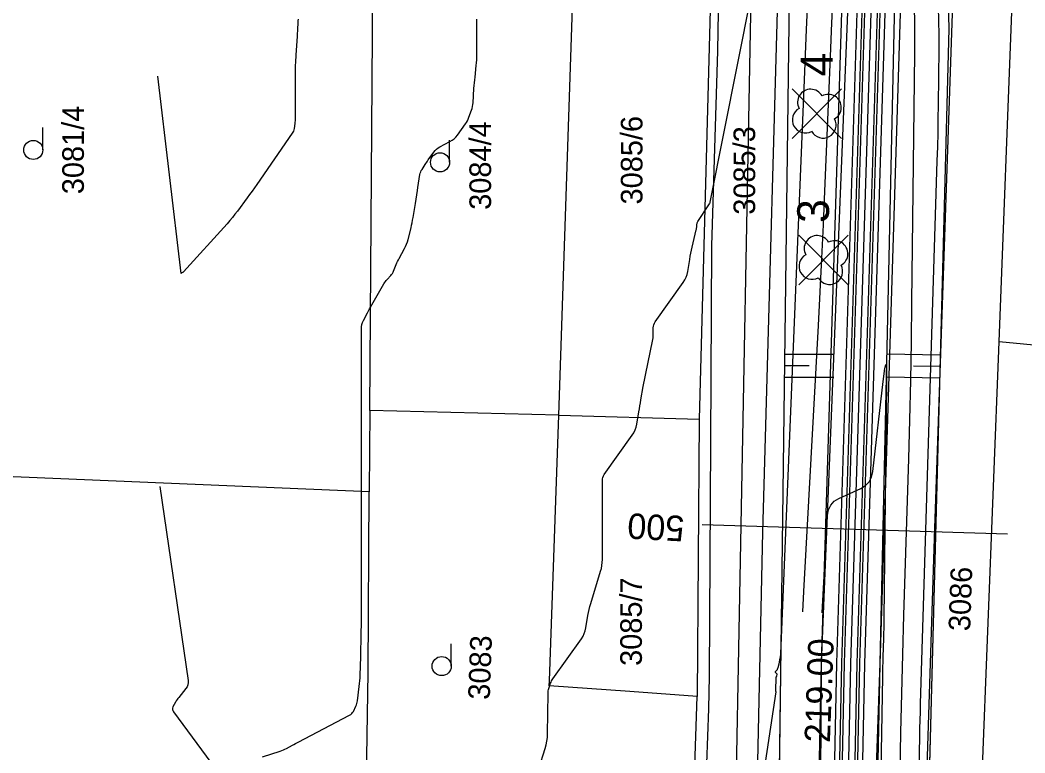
# Model space of a CAD drawing. Extents: x -534410 to -534262, y -1190162 to -1189584.
# Drawn here: x -534356.09 to -534316.62, y -1190081.68 to -1190052.88 of the extents above; entities that cross this region are included whole.
import ezdxf

# ---------------------------------------------------------------- set-up
doc = ezdxf.new("R2010")
doc.units = 0
for name, color, linetype in [('07_ELEKTRO', 7, 'Continuous'), ('30', 7, 'Continuous'), ('31', 7, 'Continuous'), ('40', 7, 'Continuous'), ('_linie', 7, 'Continuous'), ('_N_osa', 7, 'Continuous'), ('_N_tenká', 7, 'Continuous'), ('_N_tenká_velmi', 7, 'Continuous'), ('_N_text', 7, 'Continuous'), ('_přístup', 7, 'Continuous'), ('_tenka', 7, 'Continuous'), ('_velmi_tenka', 7, 'Continuous'), ('Default', 7, 'Continuous'), ('Hranice parcel', 7, 'Continuous'), ('Parcelní čísla', 7, 'Continuous'), ('Značky kultur', 7, 'Continuous')]:
    doc.layers.add(name, color=color, linetype=linetype)

msp = doc.modelspace()

# ---------------------------------------------------------------- linework, layer by layer
at = {"layer": '07_ELEKTRO'}
msp.add_lwpolyline([(-534329.31, -1190087.46), (-534329.03, -1190079.95), (-534329.01, -1190078.66), (-534328.95, -1190069.47), (-534328.91, -1190061.75), (-534328.68, -1190054.09), (-534328.55, -1190046.44), (-534328.261, -1190025.497), (-534332.174, -1190007.081), (-534334.321, -1190004.167), (-534336.852, -1190002.737), (-534339.713, -1190001.803)], dxfattribs=at)
at = {"layer": '30'}
for points in [[(-534321.439, -1190024.07), (-534321.403, -1190024.729), (-534321.16, -1190031.821), (-534321.095, -1190033.569), (-534321.018, -1190035.317), (-534320.93, -1190037.065), (-534320.831, -1190038.812), (-534320.052, -1190051.814), (-534320.024, -1190052.363), (-534320.005, -1190052.912), (-534319.997, -1190053.461), (-534319.998, -1190054.011), (-534320.024, -1190056.21), (-534320.031, -1190056.76), (-534320.042, -1190057.31), (-534320.054, -1190057.86), (-534320.07, -1190058.409), (-534320.726, -1190079.747), (-534320.736, -1190080.069), (-534320.744, -1190080.391), (-534320.751, -1190080.713), (-534320.757, -1190081.035), (-534320.78, -1190082.323)], [(-534328.187, -1190091.169), (-534326.393, -1190079.271), (-534326.393, -1190079.267), (-534326.393, -1190079.263), (-534326.394, -1190079.26), (-534326.395, -1190079.256), (-534326.4, -1190079.241), (-534326.401, -1190079.237), (-534326.402, -1190079.234), (-534326.402, -1190079.23), (-534326.403, -1190079.226), (-534326.385, -1190078.709), (-534326.384, -1190078.703), (-534326.383, -1190078.696), (-534326.381, -1190078.69), (-534326.378, -1190078.684), (-534326.357, -1190078.649), (-534326.355, -1190078.646), (-534326.343, -1190078.602), (-534326.342, -1190078.595), (-534326.343, -1190078.588), (-534326.346, -1190078.582), (-534326.35, -1190078.577), (-534326.405, -1190078.527), (-534326.413, -1190078.517), (-534326.416, -1190078.506), (-534326.414, -1190078.495), (-534326.407, -1190078.484), (-534326.342, -1190078.407), (-534326.34, -1190078.403), (-534326.338, -1190078.4), (-534326.336, -1190078.396), (-534326.335, -1190078.392), (-534326.33, -1190078.372), (-534326.327, -1190078.361), (-534326.321, -1190078.34), (-534326.318, -1190078.33), (-534326.314, -1190078.321), (-534326.301, -1190078.29), (-534326.298, -1190078.283), (-534326.296, -1190078.275), (-534326.291, -1190078.255), (-534326.288, -1190078.243), (-534326.278, -1190078.211), (-534326.276, -1190078.204), (-534326.274, -1190078.197), (-534326.273, -1190078.19), (-534326.271, -1190078.183), (-534326.227, -1190077.952), (-534326.22, -1190077.911), (-534326.214, -1190077.87), (-534326.21, -1190077.829), (-534326.208, -1190077.787), (-534325.27, -1190055.236), (-534325.189, -1190053.257), (-534325.109, -1190051.279)], [(-534346.562, -1190081.825), (-534345.87, -1190081.605), (-534345.807, -1190081.583), (-534345.746, -1190081.559), (-534345.685, -1190081.531), (-534345.626, -1190081.501), (-534345.393, -1190081.375), (-534345.335, -1190081.343), (-534345.276, -1190081.312), (-534345.217, -1190081.281), (-534345.159, -1190081.25), (-534343.147, -1190080.2), (-534343.099, -1190080.171), (-534343.059, -1190080.135), (-534343.024, -1190080.093), (-534342.997, -1190080.045), (-534342.898, -1190079.841), (-534342.875, -1190079.79), (-534342.857, -1190079.737), (-534342.843, -1190079.682), (-534342.834, -1190079.627), (-534342.762, -1190079.068), (-534342.749, -1190078.956), (-534342.739, -1190078.844), (-534342.732, -1190078.732), (-534342.727, -1190078.619), (-534342.708, -1190077.898), (-534342.708, -1190077.88), (-534342.708, -1190077.862), (-534342.708, -1190077.827), (-534342.707, -1190077.809), (-534342.707, -1190077.791), (-534342.689, -1190077.086), (-534342.687, -1190076.965), (-534342.685, -1190076.844), (-534342.683, -1190076.724), (-534342.683, -1190076.603), (-534342.683, -1190065.019), (-534342.678, -1190064.933), (-534342.663, -1190064.849), (-534342.638, -1190064.769), (-534342.602, -1190064.69), (-534342.44, -1190064.382), (-534342.4, -1190064.305), (-534342.358, -1190064.229), (-534342.316, -1190064.153), (-534342.273, -1190064.077), (-534341.796, -1190063.249), (-534341.768, -1190063.204), (-534341.738, -1190063.161), (-534341.706, -1190063.119), (-534341.671, -1190063.079), (-534341.528, -1190062.923), (-534341.494, -1190062.882), (-534341.464, -1190062.839), (-534341.439, -1190062.794), (-534341.417, -1190062.746), (-534341.309, -1190062.482), (-534341.284, -1190062.423), (-534341.257, -1190062.363), (-534341.228, -1190062.305), (-534341.198, -1190062.248), (-534340.985, -1190061.861), (-534340.942, -1190061.777), (-534340.904, -1190061.69), (-534340.873, -1190061.601), (-534340.847, -1190061.51), (-534340.732, -1190061.043), (-534340.709, -1190060.944), (-534340.687, -1190060.844), (-534340.668, -1190060.743), (-534340.65, -1190060.642), (-534340.562, -1190060.092), (-534340.534, -1190059.922), (-534340.479, -1190059.581), (-534340.461, -1190059.467), (-534340.379, -1190058.955), (-534340.367, -1190058.901), (-534340.35, -1190058.849), (-534340.328, -1190058.799), (-534340.3, -1190058.751), (-534340.178, -1190058.564), (-534340.147, -1190058.518), (-534340.116, -1190058.471), (-534340.084, -1190058.425), (-534340.052, -1190058.38), (-534339.837, -1190058.075), (-534339.787, -1190058.012), (-534339.731, -1190057.957), (-534339.668, -1190057.908), (-534339.6, -1190057.867), (-534339.204, -1190057.658), (-534339.118, -1190057.606), (-534339.039, -1190057.546), (-534338.969, -1190057.477), (-534338.905, -1190057.399), (-534338.593, -1190056.966), (-534338.551, -1190056.904), (-534338.515, -1190056.84), (-534338.483, -1190056.773), (-534338.456, -1190056.704), (-534338.356, -1190056.422), (-534338.334, -1190056.351), (-534338.316, -1190056.279), (-534338.304, -1190056.206), (-534338.296, -1190056.133), (-534338.259, -1190055.571), (-534338.251, -1190055.459), (-534338.241, -1190055.346), (-534338.231, -1190055.234), (-534338.218, -1190055.121), (-534338.166, -1190054.672), (-534338.154, -1190054.56), (-534338.146, -1190054.447), (-534338.141, -1190054.335), (-534338.14, -1190054.222), (-534338.14, -1190053.34), (-534338.14, -1190053.291), (-534338.141, -1190053.241), (-534338.141, -1190053.192), (-534338.143, -1190053.142), (-534338.148, -1190052.943), (-534338.149, -1190052.894), (-534338.15, -1190052.845)], [(-534324.582, -1190076.169), (-534324.371, -1190072.338), (-534324.333, -1190072.121), (-534324.245, -1190071.938), (-534324.108, -1190071.789), (-534323.919, -1190071.675), (-534323.067, -1190071.284), (-534322.878, -1190071.169), (-534322.734, -1190071.02), (-534322.638, -1190070.838), (-534322.588, -1190070.622), (-534322.186, -1190067.078), (-534322.121, -1190066.577), (-534322.076, -1190066.412), (-534322.053, -1190066.582), (-534322.05, -1190067.087), (-534322.157, -1190076.409), (-534322.16, -1190076.598), (-534322.163, -1190076.787), (-534322.168, -1190076.975), (-534322.173, -1190077.164), (-534322.196, -1190077.919), (-534322.202, -1190078.108), (-534322.206, -1190078.297), (-534322.211, -1190078.485), (-534322.214, -1190078.674), (-534322.64, -1190103.1)], [(-534350.597, -1190071.215), (-534349.487, -1190078.826), (-534349.483, -1190078.915), (-534349.496, -1190078.999), (-534349.528, -1190079.078), (-534349.577, -1190079.152), (-534349.858, -1190079.496), (-534349.892, -1190079.539), (-534349.923, -1190079.584), (-534349.952, -1190079.631), (-534349.979, -1190079.679), (-534350.082, -1190079.873), (-534350.1, -1190079.921), (-534350.104, -1190079.968), (-534350.093, -1190080.014), (-534350.068, -1190080.059), (-534348.04, -1190082.803)]]:
    msp.add_lwpolyline(points, dxfattribs=at)
at = {"layer": '31'}
for points in [[(-534335.714, -1190082.285), (-534335.462, -1190081.509), (-534335.421, -1190081.363), (-534335.391, -1190081.216), (-534335.372, -1190081.066), (-534335.365, -1190080.915), (-534335.35, -1190079.342), (-534335.348, -1190079.29), (-534335.341, -1190079.24), (-534335.331, -1190079.189), (-534335.316, -1190079.14), (-534335.25, -1190078.943), (-534335.231, -1190078.895), (-534335.21, -1190078.848), (-534335.184, -1190078.803), (-534335.156, -1190078.76), (-534334.039, -1190077.197), (-534333.975, -1190077.095), (-534333.923, -1190076.988), (-534333.885, -1190076.877), (-534333.859, -1190076.759), (-534333.782, -1190076.28), (-534333.76, -1190076.161), (-534333.735, -1190076.042), (-534333.705, -1190075.925), (-534333.672, -1190075.808), (-534333.283, -1190074.54), (-534333.253, -1190074.427), (-534333.231, -1190074.313), (-534333.218, -1190074.197), (-534333.214, -1190074.08), (-534333.214, -1190073.506), (-534333.214, -1190073.374), (-534333.214, -1190073.241), (-534333.214, -1190072.977), (-534333.214, -1190072.911), (-534333.214, -1190072.845), (-534333.214, -1190072.778), (-534333.214, -1190072.712), (-534333.214, -1190072.448), (-534333.214, -1190072.315), (-534333.214, -1190072.183), (-534333.214, -1190071.506), (-534333.214, -1190071.374), (-534333.214, -1190071.241), (-534333.214, -1190070.977), (-534333.21, -1190070.912), (-534333.195, -1190070.851), (-534333.171, -1190070.792), (-534333.138, -1190070.737), (-534332.038, -1190069.196), (-534331.974, -1190069.095), (-534331.923, -1190068.989), (-534331.885, -1190068.877), (-534331.859, -1190068.76), (-534331.782, -1190068.282), (-534331.762, -1190068.162), (-534331.742, -1190068.043), (-534331.721, -1190067.924), (-534331.7, -1190067.804), (-534331.607, -1190067.281), (-534331.583, -1190067.154), (-534331.559, -1190067.027), (-534331.534, -1190066.9), (-534331.508, -1190066.774), (-534331.24, -1190065.505), (-534331.228, -1190065.439), (-534331.22, -1190065.374), (-534331.214, -1190065.308), (-534331.213, -1190065.242), (-534331.213, -1190064.977), (-534331.208, -1190064.912), (-534331.193, -1190064.851), (-534331.169, -1190064.792), (-534331.135, -1190064.737), (-534330.037, -1190063.195), (-534329.974, -1190063.094), (-534329.923, -1190062.988), (-534329.884, -1190062.877), (-534329.859, -1190062.76), (-534329.782, -1190062.284), (-534329.761, -1190062.165), (-534329.739, -1190062.047), (-534329.715, -1190061.928), (-534329.688, -1190061.811), (-534329.528, -1190061.128), (-534329.522, -1190061.1), (-534329.517, -1190061.072), (-534329.512, -1190061.044), (-534329.509, -1190061.016), (-534329.497, -1190060.902), (-534329.493, -1190060.874), (-534329.485, -1190060.847), (-534329.474, -1190060.821), (-534329.46, -1190060.796), (-534329.033, -1190060.14), (-534329.011, -1190060.107), (-534328.99, -1190060.074), (-534328.985, -1190060.065), (-534328.981, -1190060.057), (-534328.977, -1190060.047), (-534328.975, -1190060.038), (-534327.353, -1190051.869)], [(-534325.339, -1190076.14), (-534325.297, -1190075.335), (-534324.723, -1190064.883), (-534324.653, -1190063.563), (-534324.587, -1190062.243), (-534324.526, -1190060.922), (-534324.469, -1190059.601), (-534324.249, -1190054.317), (-534324.195, -1190052.996), (-534324.141, -1190051.675)], [(-534320.964, -1190052.178), (-534320.949, -1190053.183), (-534320.951, -1190054.188), (-534321.064, -1190063.973), (-534321.085, -1190065.511), (-534321.114, -1190067.048), (-534321.15, -1190068.585), (-534321.193, -1190070.122), (-534321.382, -1190076.27), (-534321.427, -1190077.807), (-534321.467, -1190079.344), (-534321.501, -1190080.881), (-534321.531, -1190082.418)], [(-534345.17, -1190052.846), (-534345.178, -1190052.913), (-534345.183, -1190052.981), (-534345.192, -1190053.254), (-534345.195, -1190053.323), (-534345.198, -1190053.391), (-534345.202, -1190053.459), (-534345.206, -1190053.527), (-534345.256, -1190054.246), (-534345.26, -1190054.306), (-534345.263, -1190054.366), (-534345.266, -1190054.426), (-534345.269, -1190054.485), (-534345.277, -1190054.725), (-534345.279, -1190054.785), (-534345.281, -1190054.845), (-534345.281, -1190054.904), (-534345.282, -1190054.964), (-534345.282, -1190056.743), (-534345.283, -1190056.794), (-534345.285, -1190056.844), (-534345.29, -1190056.895), (-534345.296, -1190056.945), (-534345.325, -1190057.147), (-534345.335, -1190057.196), (-534345.351, -1190057.243), (-534345.372, -1190057.288), (-534345.398, -1190057.331), (-534346.793, -1190059.347), (-534346.885, -1190059.479), (-534346.978, -1190059.61), (-534347.072, -1190059.741), (-534347.168, -1190059.87), (-534347.551, -1190060.387), (-534347.649, -1190060.515), (-534347.749, -1190060.64), (-534347.853, -1190060.763), (-534347.959, -1190060.883), (-534349.675, -1190062.776), (-534349.681, -1190062.782), (-534349.687, -1190062.787), (-534349.694, -1190062.792), (-534349.701, -1190062.796), (-534349.74, -1190062.82), (-534349.746, -1190062.824), (-534349.754, -1190062.831), (-534349.757, -1190062.835), (-534349.761, -1190062.843), (-534349.762, -1190062.842), (-534349.762, -1190062.841), (-534350.673, -1190055.087)]]:
    msp.add_lwpolyline(points, dxfattribs=at)
at = {"layer": '_linie'}
for points in [[(-534351.8, -1189951.99), (-534346.88, -1189964.25), (-534328.11, -1190005.55), (-534325.796, -1190021.686), (-534325.86, -1190050.97), (-534326.22, -1190078.56), (-534326.79, -1190120.4), (-534329.12, -1190134.93), (-534323.49, -1190133.89), (-534321.38, -1190121.46), (-534319.59, -1190053.22), (-534320.45, -1190021.195), (-534322.75, -1190003.33), (-534340.65, -1189960.04), (-534344.52, -1189948.89)], [(-534347.45, -1189950.137), (-534345.54, -1189954.54), (-534325.02, -1190005.35), (-534322.054, -1190021.393), (-534321.72, -1190051.56), (-534322.31, -1190078.15), (-534323.81, -1190120.37), (-534326.521, -1190134.45)], [(-534328.194, -1190134.759), (-534324.85, -1190120.45), (-534324.6, -1190078.17), (-534323.54, -1190051.92), (-534323.273, -1190021.516), (-534325.81, -1190005.43), (-534346.66, -1189954.59), (-534348.342, -1189950.518)]]:
    msp.add_lwpolyline(points, dxfattribs=at)
at = {"layer": '_N_osa'}
msp.add_lwpolyline([(-534327.357, -1190134.604), (-534324.33, -1190120.41), (-534323.455, -1190078.16), (-534322.63, -1190051.74), (-534322.663, -1190021.455), (-534325.415, -1190005.39), (-534346.1, -1189954.565), (-534347.892, -1189950.326)], dxfattribs=at)
at = {"layer": '_N_tenká'}
for points in [[(-534326.133, -1190134.378), (-534323.183, -1190120.543), (-534322.305, -1190078.19), (-534321.48, -1190051.757), (-534321.513, -1190021.356), (-534324.303, -1190005.072), (-534345.038, -1189954.124), (-534346.832, -1189949.878)], [(-534328.581, -1190134.83), (-534325.477, -1190120.277), (-534324.605, -1190078.13), (-534323.78, -1190051.723), (-534323.813, -1190021.553), (-534326.527, -1190005.708), (-534347.162, -1189955.006), (-534348.951, -1189950.773)]]:
    msp.add_lwpolyline(points, dxfattribs=at)
at = {"layer": '_N_tenká_velmi'}
for points in [[(-534326.985, -1190134.536), (-534323.981, -1190120.45), (-534323.105, -1190078.169), (-534322.28, -1190051.745), (-534322.313, -1190021.425), (-534325.076, -1190005.293), (-534345.777, -1189954.431), (-534347.569, -1189950.189)], [(-534326.772, -1190134.496), (-534323.781, -1190120.474), (-534322.905, -1190078.174), (-534322.08, -1190051.748), (-534322.113, -1190021.407), (-534324.883, -1190005.238), (-534345.592, -1189954.354), (-534347.385, -1189950.112)], [(-534327.943, -1190134.713), (-534324.879, -1190120.346), (-534324.005, -1190078.146), (-534323.18, -1190051.732), (-534323.213, -1190021.502), (-534325.947, -1190005.542), (-534346.608, -1189954.776), (-534348.398, -1189950.54)], [(-534327.73, -1190134.673), (-534324.679, -1190120.37), (-534323.805, -1190078.151), (-534322.98, -1190051.735), (-534323.013, -1190021.485), (-534325.754, -1190005.487), (-534346.423, -1189954.699), (-534348.214, -1189950.462)], [(-534327.623, -1190134.654), (-534324.579, -1190120.381), (-534323.705, -1190078.154), (-534322.88, -1190051.736), (-534322.913, -1190021.476), (-534325.657, -1190005.459), (-534346.331, -1189954.661), (-534348.122, -1189950.423)], [(-534327.091, -1190134.555), (-534324.081, -1190120.439), (-534323.205, -1190078.166), (-534322.38, -1190051.744), (-534322.413, -1190021.433), (-534325.173, -1190005.321), (-534345.869, -1189954.469), (-534347.661, -1189950.228)]]:
    msp.add_lwpolyline(points, dxfattribs=at)
at = {"layer": '_N_text'}
msp.add_lwpolyline([(-534317.294, -1190073.085), (-534329.288, -1190072.711)], dxfattribs=at)
at = {"layer": '_přístup'}
for p, q in [((-534323.817, -1190057.533), (-534325.763, -1190055.587)), ((-534325.763, -1190057.533), (-534323.817, -1190055.587)), ((-534325.503, -1190063.283), (-534323.557, -1190061.337)), ((-534323.557, -1190063.283), (-534325.503, -1190061.337))]:
    msp.add_line(p, q, dxfattribs=at)
msp.add_lwpolyline([(-534330.552, -1190135.191), (-534328.648, -1190119.819), (-534326.845, -1190024.247), (-534332.805, -1189999.297), (-534354.454, -1189948.317)], dxfattribs=at)
for centre in [(-534324.79, -1190056.56), (-534324.53, -1190062.31)]:
    msp.add_circle(centre, 0.000512, dxfattribs=at)
for centre, start, end in [((-534325.035, -1190056.111), 28.6209, 208.6209), ((-534324.341, -1190056.315), 298.6209, 118.6209), ((-534325.239, -1190056.805), 118.6209, 298.6209), ((-534324.545, -1190057.009), 208.6209, 28.6209), ((-534324.775, -1190061.861), 28.6209, 208.6209), ((-534324.081, -1190062.065), 298.6209, 118.6209), ((-534324.979, -1190062.555), 118.6209, 298.6209), ((-534324.285, -1190062.759), 208.6209, 28.6209)]:
    msp.add_arc(centre, 0.512, start, end, dxfattribs=at)
at = {"layer": '_tenka'}
for points in [[(-534351.8, -1189951.99), (-534346.88, -1189964.25), (-534328.11, -1190005.55), (-534325.796, -1190021.686), (-534325.86, -1190050.97), (-534326.22, -1190078.56), (-534326.79, -1190120.4), (-534329.12, -1190134.93), (-534323.49, -1190133.89), (-534321.38, -1190121.46), (-534319.59, -1190053.22), (-534320.45, -1190021.195), (-534322.75, -1190003.33), (-534340.65, -1189960.04), (-534344.52, -1189948.89)], [(-534327.55, -1190134.64), (-534323.49, -1190133.89), (-534321.38, -1190121.46), (-534319.59, -1190053.22), (-534320.45, -1190021.195), (-534322.75, -1190003.33), (-534340.65, -1189960.04), (-534344.52, -1189948.89)], [(-534347.45, -1189950.137), (-534345.54, -1189954.54), (-534325.02, -1190005.35), (-534322.054, -1190021.393), (-534321.72, -1190051.56), (-534322.31, -1190078.15), (-534323.81, -1190120.37), (-534326.521, -1190134.45)], [(-534347.45, -1189950.137), (-534345.54, -1189954.54), (-534325.02, -1190005.35), (-534322.054, -1190021.393), (-534321.72, -1190051.56), (-534322.31, -1190078.15), (-534323.81, -1190120.37), (-534326.521, -1190134.45)], [(-534328.194, -1190134.759), (-534324.85, -1190120.45), (-534324.6, -1190078.17), (-534323.54, -1190051.92), (-534323.273, -1190021.516), (-534325.81, -1190005.43), (-534346.66, -1189954.59), (-534348.342, -1189950.518)], [(-534328.194, -1190134.759), (-534324.85, -1190120.45), (-534324.6, -1190078.17), (-534323.54, -1190051.92), (-534323.273, -1190021.516), (-534325.81, -1190005.43), (-534346.66, -1189954.59), (-534348.342, -1189950.518)], [(-534351.8, -1189951.99), (-534346.88, -1189964.25), (-534328.11, -1190005.55), (-534325.796, -1190021.686), (-534325.86, -1190050.97), (-534326.22, -1190078.56), (-534326.79, -1190120.4), (-534329.12, -1190134.93), (-534327.55, -1190134.64)]]:
    msp.add_lwpolyline(points, dxfattribs=at)
at = {"layer": '_velmi_tenka'}
for p, q in [((-534326.063, -1190066.011), (-534324.128, -1190066.008)), ((-534319.931, -1190066.048), (-534322.043, -1190066.012)), ((-534326.062, -1190066.461), (-534325.095, -1190066.459)), ((-534319.938, -1190066.498), (-534320.994, -1190066.48)), ((-534326.061, -1190066.911), (-534324.126, -1190066.908)), ((-534319.946, -1190066.948), (-534322.058, -1190066.912))]:
    msp.add_line(p, q, dxfattribs=at)
at = {"layer": 'Default'}
for p, q in [((-534325.86, -1190050.97), (-534326.22, -1190078.56)), ((-534321.38, -1190121.46), (-534319.59, -1190053.22)), ((-534326.22, -1190078.56), (-534326.79, -1190120.4))]:
    msp.add_line(p, q, dxfattribs=at)
msp.add_lwpolyline([(-534319.59, -1190053.22), (-534320.45, -1190021.195), (-534322.75, -1190003.33)], dxfattribs=at)
at = {"layer": 'Hranice parcel'}
for p, q in [((-534334.93, -1190068.41), (-534334.16, -1190045.57)), ((-534328.79, -1190045.66), (-534329.41, -1190068.56)), ((-534318.39, -1190085.1), (-534317.63, -1190065.52)), ((-534307.49, -1190066.49), (-534317.63, -1190065.52)), ((-534342.35, -1190068.22), (-534342.37, -1190071.42)), ((-534334.93, -1190068.41), (-534342.35, -1190068.22)), ((-534334.93, -1190068.41), (-534329.41, -1190068.56)), ((-534329.41, -1190068.56), (-534329.49, -1190079.46)), ((-534342.37, -1190071.42), (-534367.49, -1190070.35)), ((-534329.74, -1190087.07), (-534329.49, -1190079.46))]:
    msp.add_line(p, q, dxfattribs=at)
for points in [[(-534333.99, -1189993.03), (-534331.98, -1189997.67), (-534327.34, -1190013.08), (-534325.48, -1190021.81), (-534326.93, -1190073), (-534328.13, -1190128.3), (-534328.71, -1190131.86)], [(-534322.11, -1190134.26), (-534321.95, -1190128.7), (-534320.16, -1190072.85), (-534318.8, -1190033.53)], [(-534317.63, -1190065.52), (-534317.11, -1190052.22), (-534318.8, -1190033.53)], [(-534342.35, -1190068.22), (-534342.22, -1190049.76), (-534342.19, -1190045.44)], [(-534329.49, -1190079.46), (-534332.14, -1190079.27), (-534335.3, -1190079.04), (-534335.29, -1190078.85), (-534334.93, -1190068.41)], [(-534342.57, -1190087.3), (-534342.5, -1190083.48), (-534342.42, -1190078.52), (-534342.37, -1190071.42)]]:
    msp.add_lwpolyline(points, dxfattribs=at)
at = {"layer": 'Značky kultur'}
for p, q in [((-534355.195, -1190057.985), (-534355.195, -1190057.11)), ((-534339.217, -1190058.472), (-534339.217, -1190057.597)), ((-534339.152, -1190078.266), (-534339.152, -1190077.391))]:
    msp.add_line(p, q, dxfattribs=at)
for centre in [(-534355.57, -1190057.985), (-534339.592, -1190058.472), (-534339.527, -1190078.266)]:
    msp.add_circle(centre, 0.375, dxfattribs=at)

# ---------------------------------------------------------------- texts
at = {"layer": '40'}
msp.add_text('219.00', height=1, rotation=87.8077, dxfattribs=at).set_placement((-534324.277, -1190081.286))
at = {"layer": '_N_text'}
msp.add_text('500', height=1, rotation=176.9849, dxfattribs=at).set_placement((-534329.973, -1190072.372))
at = {"layer": '_přístup'}
for s, p in [('4', (-534324.169, -1190055.097)), ('3', (-534324.309, -1190060.852))]:
    msp.add_text(s, height=1.25, rotation=90, dxfattribs=at).set_placement(p)
at = {"layer": 'Parcelní čísla'}
for s, rotation, p in [('3081/4', 90, (-534353.583, -1190059.724)), ('3085/6', 90, (-534331.639, -1190060.127)), ('3084/4', 90, (-534337.587, -1190060.338)), ('3085/3', 90, (-534327.212, -1190060.53)), ('3086', 88, (-534318.768, -1190076.904)), ('3085/7', 90, (-534331.662, -1190078.258)), ('3083', 88, (-534337.639, -1190079.599))]:
    msp.add_text(s, height=0.85, rotation=rotation, dxfattribs=at).set_placement(p)

doc.saveas('drawing.dxf')
